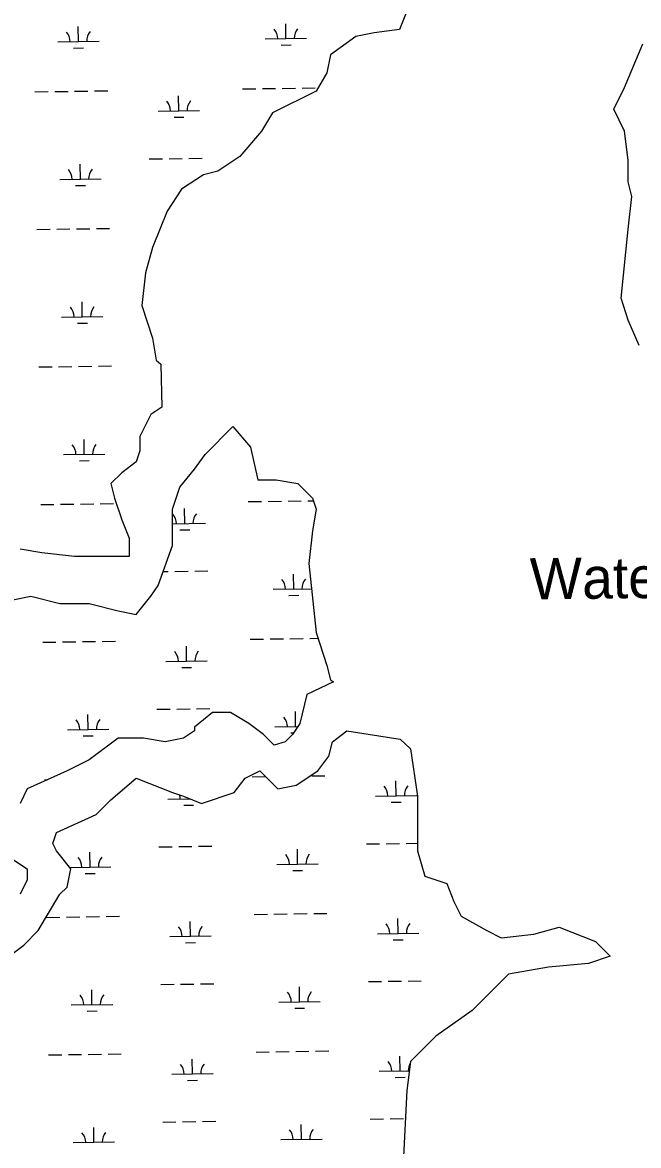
# Model space of a CAD drawing. Extents: x 3775218 to 3813389, y 343470 to 369318.
# Drawn here: x 3784812 to 3786302, y 350542 to 353257 of the extents above; entities that cross this region are included whole.
import ezdxf

# ---------------------------------------------------------------- set-up
doc = ezdxf.new("R2010")
doc.units = 0
for name, color, linetype in [('V-RIVR-IDEN', 7, 'Continuous'), ('V-TOPO-SHOR', 7, 'Continuous'), ('V-WETL-SWMP', 7, 'Continuous')]:
    doc.layers.add(name, color=color, linetype=linetype)

msp = doc.modelspace()

# ---------------------------------------------------------------- linework, layer by layer
at = {"layer": 'V-TOPO-SHOR'}
msp.add_line((3785596.8, 351545), (3785725.3, 351524.6), dxfattribs=at)
for points in [[(3785741.7, 353284.7), (3785724.1, 353240.8), (3785662.7, 353232), (3785618.7, 353223.2), (3785557.3, 353179.3), (3785548.5, 353135.4), (3785522.2, 353091.4), (3785416.8, 353038.7), (3785390.5, 352994.8), (3785337.8, 352933.3), (3785285.1, 352898.1), (3785250, 352889.3), (3785197.3, 352854.2), (3785162.2, 352801.5), (3785127, 352713.6), (3785109.5, 352652.1), (3785100.7, 352573), (3785127, 352493.9), (3785135.8, 352441.2), (3785147, 352431.5), (3785149, 352327)], [(3786303.6, 352476.4), (3786277.3, 352537.9), (3786259.7, 352590.6), (3786277.3, 352757.5), (3786286.1, 352836.6), (3786277.3, 352871.8), (3786277.3, 352924.5), (3786268.5, 352994.8), (3786242.2, 353047.5), (3786268.5, 353100.2), (3786312.4, 353205.7)], [(3785149, 352327), (3785122.6, 352309.4), (3785096.3, 352256.7), (3785096.3, 352221.6), (3785087.5, 352195.2), (3785052.4, 352168.8), (3785026.1, 352142.5), (3785034.8, 352107.3), (3785052.4, 352054.6), (3785070, 352010.7), (3785070, 351966.7), (3784938.3, 351966.7), (3784859.2, 351975.5), (3784806.5, 351984.3)], [(3784789, 351861.3), (3784832.9, 351870.1), (3784903.1, 351852.5), (3784973.4, 351852.5), (3785043.6, 351834.9), (3785087.5, 351826.2), (3785122.6, 351870.1), (3785140.2, 351896.4), (3785175.3, 351993.1), (3785175.3, 352081), (3785192.9, 352133.7), (3785228, 352177.6), (3785254.4, 352212.8), (3785321.4, 352280.8)], [(3785321.4, 352280.8), (3785364.1, 352230.3), (3785381.7, 352151.3), (3785425.6, 352151.3), (3785478.3, 352142.5), (3785513.4, 352107.3), (3785522.2, 352081), (3785513.4, 352028.2), (3785504.6, 351949.2), (3785522.2, 351782.2), (3785548.5, 351703.1), (3785557.3, 351668), (3785564.4, 351663.2)], [(3785564.4, 351663.2), (3785500.2, 351632.8), (3785482.7, 351562.5), (3785465.1, 351536.2), (3785447.5, 351518.6), (3785421.2, 351509.8), (3785394.9, 351536.2), (3785359.7, 351562.5), (3785315.8, 351588.9), (3785271.9, 351588.9), (3785228, 351553.8), (3785228, 351545), (3785201.7, 351527.4), (3785157.8, 351518.6), (3785105.1, 351527.4), (3785043.6, 351527.4), (3784973.4, 351474.7), (3784920.7, 351448.3), (3784824.1, 351404.4), (3784806.5, 351369.2)], [(3785201.7, 351386.8), (3785245.6, 351369.2), (3785324.6, 351395.6), (3785350.9, 351430.7), (3785386.1, 351448.3), (3785430, 351404.4), (3785473.9, 351413.2), (3785526.6, 351448.3), (3785552.9, 351483.5), (3785561.7, 351518.6), (3785596.8, 351545)], [(3785725.3, 351524.6), (3785750.5, 351501), (3785768, 351386.8), (3785768, 351255), (3785785.6, 351193.5), (3785838.3, 351175.9), (3785855.8, 351132), (3785873.4, 351096.8), (3785934.9, 351061.7), (3785970, 351044.1), (3786049, 351052.9), (3786110.5, 351070.5), (3786198.3, 351035.3), (3786233.4, 351000.2), (3786180.7, 350982.6), (3786084.1, 350973.8), (3785987.5, 350956.3), (3785899.7, 350868.4), (3785811.9, 350806.9), (3785750.5, 350745.4), (3785741.7, 350675.1), (3785732.9, 350499.4)], [(3784780.2, 351000.2), (3784815.3, 351026.6), (3784850.4, 351061.7), (3784903.1, 351149.6), (3784920.7, 351167.1), (3784929.5, 351211.1), (3784894.4, 351255), (3784885.6, 351272.6), (3784894.4, 351298.9), (3784990.9, 351342.9), (3785026.1, 351378), (3785087.5, 351430.7), (3785175.3, 351395.6), (3785201.7, 351386.8)], [(3784771.4, 351246.2), (3784824.1, 351211.1), (3784824.1, 351184.7), (3784806.5, 351149.6)]]:
    msp.add_lwpolyline(points, dxfattribs=at)
at = {"layer": 'V-WETL-SWMP'}
for p, q in [((3784947.7, 353211.3), (3784947.2, 353247.3)), ((3785449.5, 353218.4), (3785449, 353254.4)), ((3784897.7, 353210.6), (3784997.7, 353212)), ((3785399.5, 353217.7), (3785499.5, 353219.1)), ((3785437.8, 353202.8), (3785461.8, 353203.1)), ((3784935.9, 353195.7), (3784959.9, 353196.1)), ((3785344.4, 353096.8), (3785376.4, 353097.3)), ((3785392.4, 353097.5), (3785424.4, 353098)), ((3785440.4, 353098.2), (3785472.4, 353098.6)), ((3785488.4, 353098.9), (3785520.4, 353099.3)), ((3784842.5, 353089.7), (3784874.5, 353090.2)), ((3784890.5, 353090.4), (3784922.5, 353090.9)), ((3784938.5, 353091.1), (3784970.5, 353091.6)), ((3784986.5, 353091.8), (3785018.5, 353092.2)), ((3785190.5, 353043.9), (3785190, 353079.9)), ((3785140.5, 353043.2), (3785240.5, 353044.6)), ((3785178.8, 353028.3), (3785202.8, 353028.7)), ((3784952.4, 352878.7), (3784951.9, 352914.7)), ((3785118.8, 352927.5), (3785150.8, 352927.9)), ((3785166.8, 352928.1), (3785198.8, 352928.6)), ((3785214.8, 352928.8), (3785246.8, 352929.3)), ((3784902.4, 352878), (3785002.4, 352879.4)), ((3784940.6, 352863.1), (3784964.6, 352863.4)), ((3784847.2, 352757.1), (3784879.2, 352757.6)), ((3784895.2, 352757.8), (3784927.2, 352758.2)), ((3784943.2, 352758.5), (3784975.2, 352758.9)), ((3784991.2, 352759.1), (3785023.2, 352759.6)), ((3784957.1, 352546), (3784956.6, 352582)), ((3784907.1, 352545.3), (3785007.1, 352546.7)), ((3784945.3, 352530.4), (3784969.3, 352530.8)), ((3784851.9, 352424.5), (3784883.9, 352424.9)), ((3784899.9, 352425.1), (3784931.9, 352425.6)), ((3784947.9, 352425.8), (3784979.9, 352426.3)), ((3784995.9, 352426.5), (3785027.9, 352426.9)), ((3784961.8, 352213.4), (3784961.3, 352249.4)), ((3784911.8, 352212.7), (3785011.8, 352214.1)), ((3784950, 352197.8), (3784974, 352198.1)), ((3784856.6, 352091.8), (3784888.6, 352092.3)), ((3784904.6, 352092.5), (3784936.6, 352093)), ((3784952.6, 352093.2), (3784984.6, 352093.6)), ((3785000.6, 352093.9), (3785032.6, 352094.3)), ((3785358.5, 352098.9), (3785390.5, 352099.4)), ((3785406.5, 352099.6), (3785438.5, 352100)), ((3785454.5, 352100.3), (3785486.5, 352100.7)), ((3785502.5, 352100.9), (3785515.4, 352101.1)), ((3785204.6, 352046), (3785204.1, 352082)), ((3785175.3, 352045.6), (3785254.6, 352046.7)), ((3785192.8, 352030.4), (3785216.8, 352030.7)), ((3785152.3, 351929.8), (3785164.8, 351930)), ((3785180.8, 351930.2), (3785212.8, 351930.7)), ((3785228.8, 351930.9), (3785260.8, 351931.3)), ((3785468.3, 351887.8), (3785467.8, 351923.8)), ((3785418.3, 351887.1), (3785511, 351888.4)), ((3785456.5, 351872.2), (3785480.5, 351872.6)), ((3785363.2, 351766.3), (3785395.2, 351766.7)), ((3785411.2, 351766.9), (3785443.2, 351767.4)), ((3785459.2, 351767.6), (3785491.2, 351768.1)), ((3785507.2, 351768.3), (3785526.7, 351768.6)), ((3784861.3, 351759.2), (3784893.3, 351759.6)), ((3784909.3, 351759.9), (3784941.3, 351760.3)), ((3784957.3, 351760.5), (3784989.3, 351761)), ((3785005.3, 351761.2), (3785037.3, 351761.7)), ((3785209.3, 351713.3), (3785208.8, 351749.3)), ((3785159.3, 351712.6), (3785259.3, 351714.1)), ((3785197.5, 351697.7), (3785221.5, 351698.1)), ((3784971.2, 351548.1), (3784970.6, 351584.1)), ((3785137.5, 351596.9), (3785169.5, 351597.3)), ((3785185.5, 351597.6), (3785217.5, 351598)), ((3785233.5, 351598.2), (3785265.5, 351598.7)), ((3785473, 351555.2), (3785472.5, 351591.2)), ((3784921.2, 351547.4), (3785021.1, 351548.8)), ((3785423, 351554.5), (3785477.8, 351555.3)), ((3784959.4, 351532.5), (3784983.4, 351532.8)), ((3785461.2, 351539.6), (3785467.4, 351539.7)), ((3784866, 351426.5), (3784873, 351426.6)), ((3785367.9, 351433.6), (3785399.9, 351434.1)), ((3785511.9, 351435.7), (3785543.9, 351436.1)), ((3785715.9, 351387.8), (3785715.4, 351423.8)), ((3785665.9, 351387.1), (3785765.9, 351388.5)), ((3785164, 351380), (3785216.8, 351380.7)), ((3785202.2, 351365.1), (3785226.2, 351365.4)), ((3785214, 351380.7), (3785214, 351381.9)), ((3785704.1, 351372.2), (3785728.1, 351372.5)), ((3784975.8, 351215.5), (3784975.3, 351251.5)), ((3785142.2, 351264.2), (3785174.2, 351264.7)), ((3785190.2, 351264.9), (3785222.2, 351265.4)), ((3785238.2, 351265.6), (3785270.2, 351266.1)), ((3785477.7, 351222.5), (3785477.2, 351258.5)), ((3785644.1, 351271.3), (3785676.1, 351271.8)), ((3785692.1, 351272), (3785724.1, 351272.5)), ((3785740.1, 351272.7), (3785768, 351273.1)), ((3785427.7, 351221.8), (3785527.7, 351223.3)), ((3784926.5, 351214.8), (3785025.8, 351216.2)), ((3784964.1, 351199.9), (3784988.1, 351200.2)), ((3785465.9, 351206.9), (3785489.9, 351207.3)), ((3784870.7, 351093.9), (3784902.7, 351094.3)), ((3784918.7, 351094.6), (3784950.7, 351095)), ((3784966.7, 351095.3), (3784998.7, 351095.7)), ((3785014.7, 351095.9), (3785046.7, 351096.4)), ((3785218.7, 351048.1), (3785218.2, 351084.1)), ((3785372.6, 351101), (3785404.6, 351101.4)), ((3785420.6, 351101.7), (3785452.6, 351102.1)), ((3785468.6, 351102.3), (3785500.6, 351102.8)), ((3785516.6, 351103), (3785548.5, 351103.5)), ((3785720.6, 351055.1), (3785720.1, 351091.1)), ((3785168.7, 351047.4), (3785268.7, 351048.8)), ((3785206.9, 351032.5), (3785230.9, 351032.8)), ((3785670.6, 351054.4), (3785770.6, 351055.8)), ((3785708.8, 351039.5), (3785732.8, 351039.9)), ((3785146.9, 350931.6), (3785178.9, 350932.1)), ((3785194.9, 350932.3), (3785226.9, 350932.7)), ((3785242.9, 350933), (3785274.9, 350933.4)), ((3785482.4, 350889.9), (3785481.9, 350925.9)), ((3785648.8, 350938.7), (3785680.8, 350939.1)), ((3785696.8, 350939.4), (3785728.8, 350939.8)), ((3785744.8, 350940), (3785776.8, 350940.5)), ((3784980.5, 350882.8), (3784980, 350918.8)), ((3784930.5, 350882.1), (3785030.5, 350883.5)), ((3784968.8, 350867.2), (3784992.8, 350867.6)), ((3785432.4, 350889.2), (3785532.4, 350890.6)), ((3785470.6, 350874.3), (3785494.6, 350874.6)), ((3784875.4, 350761.3), (3784907.4, 350761.7)), ((3784923.4, 350761.9), (3784955.4, 350762.4)), ((3784971.4, 350762.6), (3785003.4, 350763.1)), ((3785019.4, 350763.3), (3785051.4, 350763.7)), ((3785377.3, 350768.3), (3785409.3, 350768.8)), ((3785425.3, 350769), (3785457.2, 350769.5)), ((3785473.2, 350769.7), (3785505.2, 350770.1)), ((3785521.2, 350770.4), (3785553.2, 350770.8)), ((3785725.3, 350722.5), (3785724.7, 350758.5)), ((3785223.4, 350715.4), (3785222.9, 350751.4)), ((3785173.4, 350714.7), (3785273.4, 350716.1)), ((3785675.3, 350721.8), (3785747.6, 350722.8)), ((3785713.5, 350706.9), (3785737.5, 350707.2)), ((3785211.6, 350699.8), (3785235.6, 350700.2)), ((3785151.6, 350599), (3785183.6, 350599.4)), ((3785199.6, 350599.6), (3785231.6, 350600.1)), ((3785247.6, 350600.3), (3785279.6, 350600.8)), ((3785653.5, 350606), (3785685.5, 350606.5)), ((3785701.5, 350606.7), (3785733.5, 350607.2)), ((3784985.2, 350550.2), (3784984.7, 350586.2)), ((3785487.1, 350557.3), (3785486.6, 350593.3)), ((3784935.2, 350549.5), (3785035.2, 350550.9)), ((3785437.1, 350556.6), (3785537.1, 350558))]:
    msp.add_line(p, q, dxfattribs=at)
for points in [[(3785741.7, 353284.7), (3785724.1, 353240.8), (3785662.7, 353232), (3785618.7, 353223.2), (3785557.3, 353179.3), (3785548.5, 353135.4), (3785522.2, 353091.4), (3785416.8, 353038.7), (3785390.5, 352994.8), (3785337.8, 352933.3), (3785285.1, 352898.1), (3785250, 352889.3), (3785197.3, 352854.2), (3785162.2, 352801.5), (3785127, 352713.6), (3785109.5, 352652.1), (3785100.7, 352573), (3785127, 352493.9), (3785135.8, 352441.2), (3785147, 352431.5), (3785149, 352327), (3785122.6, 352309.4), (3785096.3, 352256.7), (3785096.3, 352221.6), (3785087.5, 352195.2), (3785052.4, 352168.8), (3785026.1, 352142.5), (3785034.8, 352107.3), (3785052.4, 352054.6), (3785070, 352010.7), (3785070, 351966.7), (3784938.3, 351966.7), (3784859.2, 351975.5), (3784806.5, 351984.3)], [(3786303.6, 352476.4), (3786277.3, 352537.9), (3786259.7, 352590.6), (3786277.3, 352757.5), (3786286.1, 352836.6), (3786277.3, 352871.8), (3786277.3, 352924.5), (3786268.5, 352994.8), (3786242.2, 353047.5), (3786268.5, 353100.2), (3786312.4, 353205.7)], [(3784789, 351861.3), (3784832.9, 351870.1), (3784903.1, 351852.5), (3784973.4, 351852.5), (3785043.6, 351834.9), (3785087.5, 351826.2), (3785122.6, 351870.1), (3785140.2, 351896.4), (3785175.3, 351993.1), (3785175.3, 352081), (3785192.9, 352133.7), (3785228, 352177.6), (3785254.4, 352212.8), (3785321.4, 352280.8), (3785364.1, 352230.3), (3785381.7, 352151.3), (3785425.6, 352151.3), (3785478.3, 352142.5), (3785513.4, 352107.3), (3785522.2, 352081), (3785513.4, 352028.2), (3785504.6, 351949.2), (3785522.2, 351782.2), (3785548.5, 351703.1), (3785557.3, 351668), (3785564.4, 351663.2), (3785500.2, 351632.8), (3785482.7, 351562.5), (3785465.1, 351536.2), (3785447.5, 351518.6), (3785421.2, 351509.8), (3785394.9, 351536.2), (3785359.7, 351562.5), (3785315.8, 351588.9), (3785271.9, 351588.9), (3785228, 351553.8), (3785228, 351545), (3785201.7, 351527.4), (3785157.8, 351518.6), (3785105.1, 351527.4), (3785043.6, 351527.4), (3784973.4, 351474.7), (3784920.7, 351448.3), (3784824.1, 351404.4), (3784806.5, 351369.2)], [(3785201.7, 351386.8), (3785245.6, 351369.2), (3785324.6, 351395.6), (3785350.9, 351430.7), (3785386.1, 351448.3), (3785430, 351404.4), (3785473.9, 351413.2), (3785526.6, 351448.3), (3785552.9, 351483.5), (3785561.7, 351518.6), (3785596.8, 351545), (3785725.3, 351524.6)], [(3785725.3, 351524.6), (3785750.5, 351501), (3785768, 351386.8), (3785768, 351255), (3785785.6, 351193.5), (3785838.3, 351175.9), (3785855.8, 351132), (3785873.4, 351096.8), (3785934.9, 351061.7), (3785970, 351044.1), (3786049, 351052.9), (3786110.5, 351070.5), (3786198.3, 351035.3), (3786233.4, 351000.2), (3786180.7, 350982.6), (3786084.1, 350973.8), (3785987.5, 350956.3), (3785899.7, 350868.4), (3785811.9, 350806.9), (3785750.5, 350745.4), (3785741.7, 350675.1), (3785732.9, 350499.4)], [(3784780.2, 351000.2), (3784815.3, 351026.6), (3784850.4, 351061.7), (3784903.1, 351149.6), (3784920.7, 351167.1), (3784929.5, 351211.1), (3784894.4, 351255), (3784885.6, 351272.6), (3784894.4, 351298.9), (3784990.9, 351342.9), (3785026.1, 351378), (3785087.5, 351430.7), (3785175.3, 351395.6), (3785201.7, 351386.8)], [(3784771.4, 351246.2), (3784824.1, 351211.1), (3784824.1, 351184.7), (3784806.5, 351149.6)]]:
    msp.add_lwpolyline(points, dxfattribs=at)
for centre, start, end in [((3784892.4, 353211), 0.0365, 41.5802), ((3785002.9, 353212.6), 140.0365, 181.5802), ((3785394.3, 353218.1), 0.0365, 41.5802), ((3785504.8, 353219.7), 140.0365, 181.5802), ((3785135.3, 353043.6), 0.0365, 41.5802), ((3785245.8, 353045.2), 140.0365, 181.5802), ((3784897.1, 352878.4), 0.0365, 41.5802), ((3785007.6, 352879.9), 140.0365, 181.5802), ((3784901.8, 352545.7), 0.0365, 41.5802), ((3785012.3, 352547.3), 140.0365, 181.5802), ((3784906.5, 352213.1), 0.0365, 41.5802), ((3785017, 352214.6), 140.0365, 181.5802), ((3785149.4, 352045.7), 0.0365, 41.5802), ((3785259.9, 352047.2), 140.0365, 181.5802), ((3785413.1, 351887.5), 0.0365, 41.5802), ((3785523.5, 351889.1), 140.0365, 181.5802), ((3785154.1, 351713), 0.0365, 41.5802), ((3785264.5, 351714.6), 140.0365, 181.5802), ((3785417.8, 351554.9), 0.0365, 41.5802), ((3784915.9, 351547.8), 0.0365, 41.5802), ((3785026.4, 351549.4), 140.0365, 181.5802), ((3785660.6, 351387.5), 0.0365, 41.5802), ((3785771.1, 351389), 140.0365, 181.5802), ((3785158.8, 351380.4), 0.0365, 15.4662), ((3785532.9, 351223.8), 140.0365, 181.5802), ((3784920.6, 351215.2), 0.0365, 41.5802), ((3785031.1, 351216.7), 140.0365, 181.5802), ((3785422.5, 351222.2), 0.0365, 41.5802), ((3785163.5, 351047.8), 0.0365, 41.5802), ((3785273.9, 351049.3), 140.0365, 181.5802), ((3785665.3, 351054.8), 0.0365, 41.5802), ((3785775.8, 351056.4), 140.0365, 181.5802), ((3784925.3, 350882.5), 0.0365, 41.5802), ((3785035.8, 350884.1), 140.0365, 181.5802), ((3785427.2, 350889.6), 0.0365, 41.5802), ((3785537.6, 350891.2), 140.0365, 181.5802), ((3785168.2, 350715.1), 0.0365, 41.5802), ((3785278.6, 350716.7), 140.0365, 181.5802), ((3785670, 350722.2), 0.0365, 41.5802), ((3785780.5, 350723.8), 150.0104, 181.5802), ((3784930, 350549.9), 0.0365, 41.5802), ((3785040.5, 350551.4), 140.0365, 181.5802), ((3785431.8, 350557), 0.0365, 41.5802), ((3785542.3, 350558.5), 140.0365, 181.5802)]:
    msp.add_arc(centre, 35.2, start, end, dxfattribs=at)

# ---------------------------------------------------------------- texts
at = {"layer": 'V-RIVR-IDEN'}
msp.add_text('Water', height=100, rotation=0.7588, dxfattribs=at).set_placement((3786040, 351862.2))

doc.saveas('drawing.dxf')
